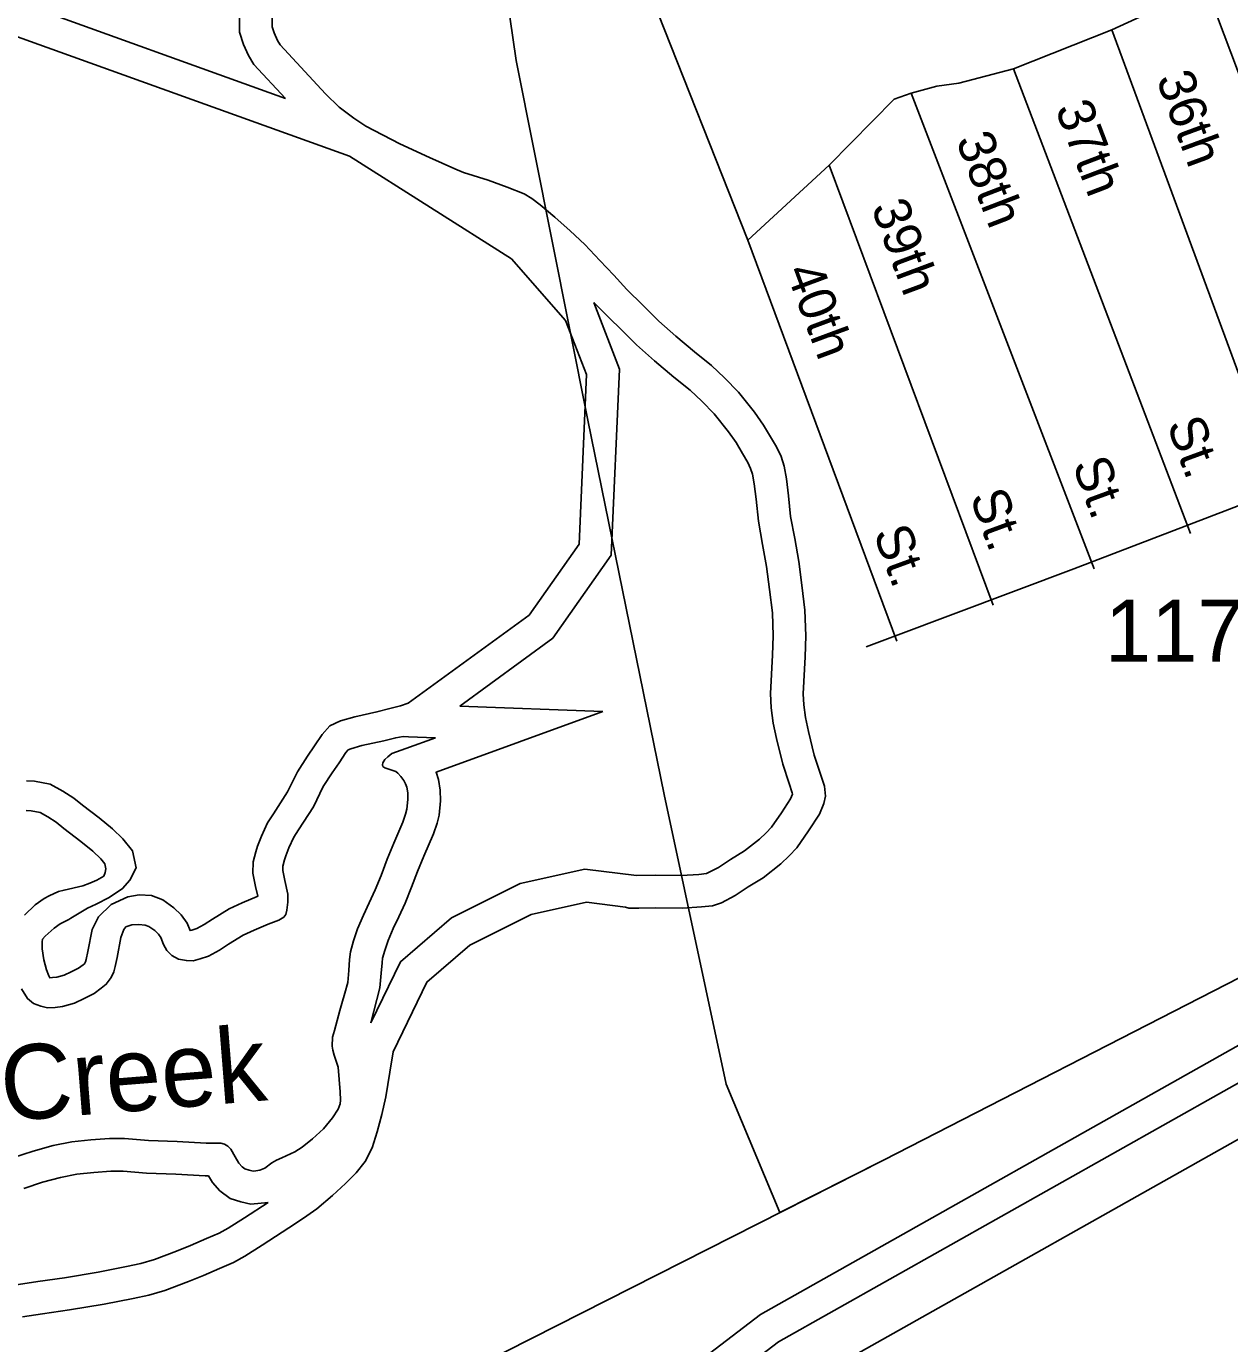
# Model space of a CAD drawing. Extents: x 2104537 to 2336408, y 34176 to 229611.
# Drawn here: x 2145145 to 2147565, y 41128 to 43777 of the extents above; entities that cross this region are included whole.
import ezdxf

# ---------------------------------------------------------------- set-up
doc = ezdxf.new("R2010")
doc.units = 0
for name, color, linetype in [('Exist Boundary Political City Limit New', 7, 'Continuous'), ('Exist Boundary Political CountyLine', 7, 'Continuous'), ('Exist Hydrographic Buffer Line', 7, 'Continuous'), ('Exist Hydrographic Creek Single Shore', 7, 'Continuous'), ('Exist Road Non-System Type 51', 7, 'Continuous'), ('Exist Road Non-System Type 51 Label', 7, 'Continuous'), ('Exist Road Secondary Type 51 Attributed', 7, 'Continuous'), ('Exist Road Secondary Type 51 Number Label', 7, 'Continuous'), ('Map Preparation Boundary City Limit Buffer Line', 7, 'Continuous'), ('Old_Level_32', 7, 'Continuous')]:
    doc.layers.add(name, color=color, linetype=linetype)

msp = doc.modelspace()

# ---------------------------------------------------------------- linework, layer by layer
at = {"layer": 'Exist Boundary Political City Limit New'}
msp.add_lwpolyline([(2143085.8, 47016.9), (2145986.8, 47681.1), (2146086.8, 47361.1), (2146166.2, 47129.6), (2146175, 46955.4), (2146187.5, 46359.1), (2146195.8, 46017.4), (2146198.2, 45916.6), (2146204.2, 45676.7), (2146209.5, 44906.5), (2146130.2, 44263.2), (2146119.2, 44174.1), (2146105.8, 43879.9), (2146130.2, 43707.9), (2146274.5, 42985), (2146428, 42232), (2146552.8, 41649.5), (2146660.8, 41391.6), (2146869, 41497.1), (2147586, 41864.5)], dxfattribs=at)
at = {"layer": 'Exist Boundary Political CountyLine'}
msp.add_lwpolyline([(2150703.7, 43176.9), (2150010.2, 42891.1), (2149584.8, 42733.6), (2149077.8, 42558.6), (2148419.3, 42255.3), (2147585.9, 41864.5), (2146869.1, 41497.1), (2145453, 40779.7), (2145039.2, 40534.7), (2144194.2, 40062.2), (2143564.8, 39648.1), (2143226.8, 39461.5), (2143110.3, 39426.5), (2143022.9, 39449.8), (2142976.2, 39508.1), (2142830.6, 39350.7), (2142457.6, 39088.2), (2141839.9, 38749.9), (2141018.2, 38295), (2140254.7, 37880.8), (2139280.4, 37214)], dxfattribs=at)
at = {"layer": 'Exist Hydrographic Buffer Line'}
for points in [[(2145595.4, 43866.2), (2145585, 43846.2), (2145577.3, 43823.6), (2145573.7, 43800.4), (2145574.2, 43765.4), (2145582.3, 43740.2), (2145592, 43718.3), (2145603, 43700.1), (2145666.3, 43631.6)], [(2145666.3, 43631.6), (2145123, 43827.2), (2144999.6, 43829.5), (2144342.6, 43750.5), (2144081.2, 43763.4)], [(2145416.5, 40247.5), (2145659.9, 40368.7), (2146658.2, 41131.5), (2147665.8, 41698.9), (2149090.1, 42351.2), (2149952.3, 42638.3), (2151907.1, 43246.7)], [(2146204.3, 42546.5), (2146321.7, 42713.6), (2146338.1, 43087.4), (2146286.5, 43221.4)], [(2146286.5, 43221.4), (2146372.5, 43136.4), (2146408.4, 43104.4), (2146447.7, 43071.5), (2146480.6, 43045.1), (2146503.6, 43023.4), (2146528.5, 42997.6), (2146557.5, 42961.8), (2146572.6, 42939.9), (2146585.6, 42917.7), (2146596.2, 42900.1), (2146601.9, 42888.1), (2146605.6, 42876.4), (2146609.3, 42856.8), (2146613.2, 42825.8), (2146617.5, 42782.1), (2146626.2, 42735.2), (2146633.9, 42690.9), (2146640, 42644.7), (2146645.9, 42597.5), (2146647.6, 42551.4), (2146646, 42512.3), (2146642.1, 42435.2), (2146643.2, 42406.8), (2146647.4, 42375.8), (2146654.2, 42344.6), (2146666.6, 42293), (2146679.8, 42254.3), (2146685.8, 42235.9), (2146686.1, 42232.8), (2146682.3, 42223.8), (2146664, 42195.5), (2146643.7, 42166.4), (2146633.3, 42155.2), (2146619.8, 42142.5), (2146589.8, 42118.7), (2146561.6, 42101.8), (2146537.6, 42085.6), (2146513.5, 42073.3)], [(2146017, 42410.2), (2146204.3, 42546.5)], [(2146017, 42410.2), (2146305, 42399.4)], [(2146305, 42399.4), (2145969.4, 42277), (2145974.4, 42262.4), (2145977.6, 42241.2), (2145978.3, 42219.8), (2145975.3, 42191), (2145971.2, 42174.6), (2145964.3, 42153.3), (2145944.9, 42108.1), (2145931.8, 42077.7), (2145920, 42046), (2145907.2, 42014), (2145894.2, 41986.5), (2145883.3, 41963), (2145872.8, 41938.9), (2145866.3, 41918.9), (2145861.9, 41903.1), (2145860.8, 41893.6), (2145859.1, 41872.8), (2145856.5, 41843.2), (2145838.3, 41773)], [(2145838.3, 41773), (2145897.6, 41896), (2146000.6, 41984.3), (2146138.5, 42053.3), (2146268.6, 42082.2), (2146372.2, 42069.4)], [(2146513.5, 42073.3), (2146497.8, 42071.7), (2146463.2, 42069.4), (2146411, 42069.8), (2146372.2, 42069.4)], [(2145631.3, 41411.9), (2145596.8, 41408.8), (2145576.9, 41413.3), (2145555, 41419.7), (2145534.2, 41435.4), (2145519.5, 41452.2), (2145511.5, 41465.4), (2145505, 41465.4), (2145445.7, 41468.9), (2145386.7, 41471.1), (2145340.2, 41475.1), (2145315.4, 41474.8), (2145280.7, 41472.4), (2145246.5, 41468.7), (2145213.9, 41462.2), (2145177.9, 41452.6), (2145140, 41440)], [(2145631.3, 41411.9), (2145584.1, 41381.2), (2145551.3, 41360.3), (2145533.2, 41350.4), (2145507.6, 41339.8), (2145475.7, 41325.6), (2145447.4, 41313.8), (2145402.9, 41297), (2145375.8, 41289.2), (2145347, 41283.2), (2145290, 41272.1), (2145221.8, 41260.6), (2145168.6, 41252.9), (2145129.7, 41247.3), (2145080, 41242), (2145035.1, 41238.7), (2145002.3, 41236.3), (2144976.7, 41236.8), (2144906.6, 41240.8), (2144826.5, 41242.3), (2144725.4, 41241.9)]]:
    msp.add_lwpolyline(points, dxfattribs=at)
at = {"layer": 'Exist Hydrographic Creek Single Shore'}
for points in [[(2145639.4, 43795.8), (2145639.7, 43776.1), (2145643.7, 43763.6), (2145650.3, 43748.7), (2145655.7, 43739.7), (2145746.8, 43641.3)], [(2146156.9, 42593.1), (2146257, 42735.6), (2146272, 43076.6), (2146229.9, 43185.6), (2146121, 43309.2), (2145795, 43515.6), (2145110.9, 43761.8), (2145002.9, 43763.9), (2144344.9, 43684.7), (2144098.9, 43696.9)], [(2145746.8, 43641.3), (2145774.1, 43614.4), (2145804.2, 43592.5), (2145828.1, 43576.3), (2145896.3, 43540.5), (2145956.2, 43513.1), (2146006.9, 43490.1), (2146024.5, 43483.2), (2146074.4, 43467.5), (2146112.5, 43453.6), (2146146.7, 43439.9), (2146161.6, 43430.4), (2146178.5, 43417.9), (2146208.5, 43393.4), (2146238.8, 43365.9), (2146268.8, 43338.1), (2146299, 43305.7), (2146327, 43276.3), (2146353, 43247.9), (2146385.2, 43216.1), (2146417.4, 43184.3), (2146451.3, 43154.1), (2146489.4, 43122.2), (2146523.6, 43094.6), (2146549.7, 43070.2), (2146577.7, 43041.1), (2146610.1, 43001.1), (2146628, 42975.1), (2146641.9, 42951.2), (2146654, 42931.3), (2146663.2, 42912.1), (2146669.4, 42892.3), (2146674.1, 42867), (2146678.4, 42833.1), (2146682.5, 42791.3), (2146690.8, 42746.9), (2146698.8, 42700.8), (2146705.1, 42653.1), (2146711.3, 42602.8), (2146713.3, 42551.2), (2146711.5, 42509.2), (2146707.8, 42434.8), (2146708.7, 42412.5), (2146712.1, 42387.2), (2146718.1, 42359.2), (2146729.7, 42311.4), (2146742.1, 42275), (2146750.5, 42249.3), (2146752.4, 42228.9), (2146749.5, 42214.2), (2146740.5, 42193), (2146718.5, 42159), (2146694.9, 42125), (2146679.8, 42108.9), (2146662.8, 42092.8), (2146627.1, 42064.6), (2146596.9, 42046.5), (2146571, 42029), (2146543.2, 42014.7), (2146525.3, 42008.5)], [(2145384.1, 40304.6), (2145625, 40424.7), (2146622, 41186.4), (2147636, 41757.4), (2149066, 42412.3), (2149932.1, 42700.8), (2151888.7, 43309.7)], [(2145465.1, 40161.7), (2145712.2, 40284.8), (2146712.5, 41049.1), (2147710.5, 41611.1), (2149126.2, 42259.5), (2149982.4, 42544.7), (2151934.6, 43152.2)], [(2145145.8, 42259.7), (2145161.4, 42259.4), (2145193.5, 42252.9), (2145218.9, 42239), (2145240.6, 42225.1), (2145257.9, 42210.8), (2145291.6, 42185.1), (2145318.7, 42163.3), (2145339.5, 42143), (2145358.6, 42119.1), (2145365.9, 42084.8), (2145353.7, 42060.1), (2145338.8, 42043.2), (2145311.7, 42025.4), (2145285.9, 42011.9), (2145268.3, 42003.7), (2145234.9, 41983.3), (2145230.7, 41980.8), (2145218.4, 41975), (2145213, 41972.1), (2145201, 41963.6), (2145183.3, 41947.3), (2145177.8, 41941.4), (2145177.2, 41936), (2145177.4, 41921.9), (2145180.4, 41899.9), (2145185.8, 41880), (2145190.2, 41867.4), (2145192.4, 41863.9), (2145192.8, 41863.8), (2145197.9, 41864), (2145206.6, 41865.2), (2145221.4, 41869), (2145235.1, 41875.5), (2145250.4, 41883.4), (2145259.5, 41890.1), (2145261.9, 41892), (2145263.5, 41894.3), (2145264.3, 41896.1), (2145265.5, 41900.6), (2145269.1, 41916.6), (2145277.8, 41960.6), (2145290.2, 41986.4), (2145315.8, 42011.2), (2145349.2, 42026.6), (2145372.5, 42030.6), (2145396.8, 42028.9), (2145419.6, 42020.5), (2145442.1, 42004.6), (2145456.6, 41990.2), (2145468.6, 41973.5), (2145474.6, 41958.5), (2145477.9, 41959.4), (2145488.2, 41962.6), (2145502.8, 41970.7), (2145519.4, 41981.6), (2145553.1, 42002.4), (2145579.1, 42014.4), (2145609.7, 42027.4), (2145610.6, 42027.7), (2145606.4, 42047.5), (2145601.1, 42074.1), (2145601.6, 42096.7), (2145607.1, 42117.2), (2145610.2, 42128.1), (2145618.5, 42148.6), (2145630.6, 42175.2), (2145642.1, 42193.6), (2145670.5, 42237.3), (2145690.3, 42277.9), (2145710.7, 42309.2), (2145724.8, 42329.8), (2145740.4, 42352.8), (2145755.6, 42370.5), (2145777, 42380.7), (2145805.7, 42388.6), (2145850.2, 42398.4), (2145876, 42405), (2145897.8, 42410.8), (2145913.5, 42416.1), (2146156.9, 42593.1)], [(2145968.1, 42346.4), (2145908.3, 42324.6), (2145880.2, 42314.6), (2145872.2, 42308.2), (2145866.2, 42302.4), (2145862.2, 42295.9), (2145861.4, 42292), (2145862.3, 42288.7), (2145866.2, 42286), (2145876.3, 42282.5), (2145888.4, 42278.4), (2145892.3, 42275), (2145898.4, 42268.3), (2145904.5, 42260.7), (2145907.9, 42254), (2145910.4, 42246.8), (2145912.2, 42235.3), (2145912.6, 42222.1), (2145910.6, 42202.5), (2145908.1, 42192.7), (2145902.8, 42176.4), (2145884.6, 42134.1), (2145870.9, 42102.2), (2145858.8, 42069.6), (2145847.1, 42040.3), (2145834.7, 42014.3), (2145823.4, 41989.9), (2145811.4, 41962.2), (2145803.4, 41937.8), (2145797.4, 41915.9), (2145795.5, 41900.2), (2145793.7, 41878.2), (2145791.6, 41854.3), (2145785.9, 41832.5), (2145780, 41811.9), (2145775.8, 41798.2), (2145770.1, 41777.6), (2145764.8, 41757.4), (2145761.3, 41744.3), (2145760.3, 41726.3), (2145761.4, 41718.1), (2145764.2, 41708.2), (2145772.3, 41684.1), (2145774.4, 41659.4), (2145776.5, 41634.1), (2145777.2, 41617.7), (2145776.7, 41610.2), (2145772.6, 41599.7), (2145760.8, 41581.9), (2145742.6, 41560), (2145720.6, 41540.1), (2145699.9, 41523.1), (2145685, 41513.5), (2145658.8, 41501.9), (2145648.6, 41497.1), (2145638.9, 41491.4), (2145625, 41481.2), (2145615, 41477.1), (2145607.1, 41475.6), (2145601.2, 41475.1), (2145593.4, 41476.9), (2145584.9, 41479.3), (2145579.1, 41483.7), (2145572.6, 41491.1), (2145565, 41503.7), (2145556.8, 41519.3), (2145550.7, 41525.3), (2145543.5, 41529.4), (2145536.7, 41531.1), (2145506.8, 41531), (2145448.8, 41534.5), (2145390.8, 41536.6), (2145342.6, 41540.8), (2145312.7, 41540.4), (2145275, 41537.8), (2145236.5, 41533.6), (2145198.9, 41526.2), (2145159, 41515.4), (2145117.1, 41501.5)], [(2145135.8, 41841.7), (2145147.9, 41821.8), (2145159.8, 41811.7), (2145174.2, 41806.5), (2145187.9, 41803.6), (2145203.3, 41804.3), (2145218.1, 41806.3), (2145241.9, 41812.4), (2145261.7, 41821.9), (2145281.9, 41832.3), (2145295.9, 41842.6), (2145305.9, 41850.6), (2145315.7, 41864.5), (2145320.9, 41875.9), (2145323.7, 41886.3), (2145327.6, 41904.3), (2145335.6, 41944.5), (2145341.5, 41960.8), (2145345.6, 41966.3), (2145357.5, 41970.3), (2145371.2, 41970.7), (2145384, 41969.8), (2145391.5, 41967.1), (2145403.5, 41958.6), (2145410.9, 41951.3), (2145415.7, 41944.6), (2145421.3, 41930.4), (2145427.7, 41918.8), (2145437.6, 41908.7), (2145451.6, 41901.3), (2145467.3, 41898.3), (2145480.7, 41898.1), (2145494.9, 41902.1), (2145511.8, 41907.3), (2145533.7, 41919.4), (2145551.6, 41931.2), (2145581.5, 41949.6), (2145603.3, 41959.7), (2145631.5, 41971.6), (2145653.3, 41979.4), (2145663.2, 41985.8), (2145666.9, 41991.3), (2145669.4, 41999.4), (2145671.4, 42015.8), (2145671, 42031.6), (2145665, 42059.6), (2145661.1, 42079.3), (2145661.3, 42088.2), (2145664.8, 42101.2), (2145666.9, 42108.7), (2145673.5, 42125), (2145683.4, 42146.8), (2145692.5, 42161.4), (2145722.6, 42207.7), (2145742.5, 42248.4), (2145760.4, 42275.9), (2145774.2, 42296), (2145788.1, 42316.4), (2145792.8, 42321.9), (2145798.1, 42324.4), (2145820.2, 42330.5), (2145864, 42340.2), (2145888.1, 42346.3), (2145902.9, 42348.6), (2145914, 42348.4), (2145968.1, 42346.4)], [(2145144.7, 42199.9), (2145154.8, 42199.7), (2145172.8, 42196), (2145188.4, 42187.5), (2145205.3, 42176.7), (2145220.8, 42163.9), (2145254.7, 42138), (2145278.9, 42118.5), (2145295, 42102.8), (2145303.1, 42092.8), (2145305.2, 42082.9), (2145304, 42075.4), (2145300.9, 42068.2), (2145287, 42060.3), (2145272.8, 42054), (2145259.2, 42048.4), (2145221, 42040.2), (2145209.8, 42037.2), (2145191.2, 42028.3), (2145181.3, 42023), (2145163.3, 42010.2), (2145141.3, 41989.9)], [(2145883.1, 41714.8), (2145950.7, 41855.2), (2146037.2, 41929.3), (2146160.6, 41991), (2146271.8, 42015.7), (2146350.4, 42006)], [(2146525.3, 42008.5), (2146503.3, 42006.3), (2146465.2, 42003.8), (2146411.1, 42004.2), (2146377.2, 42003.8), (2146357.2, 42003.5), (2146350.4, 42006)], [(2145883.1, 41714.8), (2145876.4, 41673.9), (2145868.6, 41624.1), (2145860, 41588.9), (2145850.8, 41553.9), (2145840.7, 41522), (2145827, 41494.4), (2145808.8, 41471.7), (2145787.1, 41450.2), (2145761, 41426.1), (2145729.4, 41399.4), (2145702.7, 41380.3), (2145673.5, 41361.1), (2145619.7, 41326.1), (2145584.8, 41303.8), (2145561.6, 41291.1), (2145533.5, 41279.5), (2145501.7, 41265.4), (2145471.6, 41252.8), (2145423.7, 41234.7), (2145391.6, 41225.5), (2145360, 41218.9), (2145301.7, 41207.5), (2145231.9, 41195.8), (2145178, 41187.9), (2145137.8, 41182.2)]]:
    msp.add_lwpolyline(points, dxfattribs=at)
at = {"layer": 'Exist Road Non-System Type 51'}
for p, q in [((2146596.4, 43347.2), (2146347.7, 43974.1)), ((2147518.1, 43857), (2147328.4, 43770.1)), ((2147876.1, 42902.8), (2147518.1, 43857)), ((2147328.4, 43770.1), (2147130.7, 43691.3)), ((2147328.4, 43770.1), (2147676.4, 42826)), ((2147486.7, 42757.1), (2147130.7, 43691.3)), ((2146925, 43642.4), (2147293.1, 42686)), ((2146759.8, 43497.9), (2146596.4, 43347.2)), ((2147089.5, 42613.2), (2146759.8, 43497.9)), ((2146895.9, 42540.5), (2146596.4, 43347.2))]:
    msp.add_line(p, q, dxfattribs=at)
for points in [[(2147130.7, 43691.3), (2147020.9, 43662.9), (2146976.8, 43656.8), (2146925, 43642.4)], [(2146925, 43642.4), (2146891, 43630.3), (2146759.8, 43497.9)]]:
    msp.add_lwpolyline(points, dxfattribs=at)
at = {"layer": 'Exist Road Secondary Type 51 Attributed'}
msp.add_lwpolyline([(2146834.4, 42529.1), (2146893.1, 42551.1), (2147251.8, 42686), (2147645.4, 42836.9), (2148042.2, 42986.1), (2148435.8, 43135.4), (2148827.9, 43283.1), (2149024.7, 43357.7), (2149224.6, 43435.5), (2149427.8, 43511.7), (2149564.3, 43567.3), (2149651.2, 43594.2)], dxfattribs=at)
at = {"layer": 'Map Preparation Boundary City Limit Buffer Line'}
msp.add_lwpolyline([(2143085.8, 47016.9), (2145986.8, 47681.1), (2146086.8, 47361.1), (2146166.2, 47129.6), (2146175, 46955.4), (2146187.5, 46359.1), (2146195.8, 46017.4), (2146198.2, 45916.6), (2146204.2, 45676.7), (2146209.5, 44906.5), (2146130.2, 44263.2), (2146119.2, 44174.1), (2146105.8, 43879.9), (2146130.2, 43707.9), (2146274.5, 42985), (2146428, 42232), (2146552.8, 41649.5), (2146660.8, 41391.6), (2146869, 41497.1), (2147586, 41864.5)], dxfattribs=at)

# ---------------------------------------------------------------- texts
at = {"layer": 'Exist Road Non-System Type 51 Label'}
for s, rotation, p in [('36th', 290.2313, (2147417.1, 43671.7)), ('37th', 290.8636, (2147213.7, 43611.7)), ('38th', 291.0504, (2147014, 43548.1)), ('39th', 290.441, (2146843.8, 43413.4)), ('40th', 290.3635, (2146672.1, 43284.7)), ('St.', 290.1443, (2147438.4, 42976.8)), ('St.', 290.1443, (2147248.4, 42895.9)), ('St.', 290.1443, (2147042.2, 42831.2)), ('St.', 290.1443, (2146848.1, 42758.4))]:
    msp.add_text(s, height=75, rotation=rotation, dxfattribs=at).set_placement(p)
at = {"layer": 'Exist Road Secondary Type 51 Number Label'}
msp.add_text('1177', height=125, dxfattribs=at).set_placement((2147314.7, 42499.3))
at = {"layer": 'Old_Level_32'}
msp.add_text('Creek', height=150, rotation=4.5737, dxfattribs=at).set_placement((2145098.9, 41574.8))

doc.saveas('drawing.dxf')
